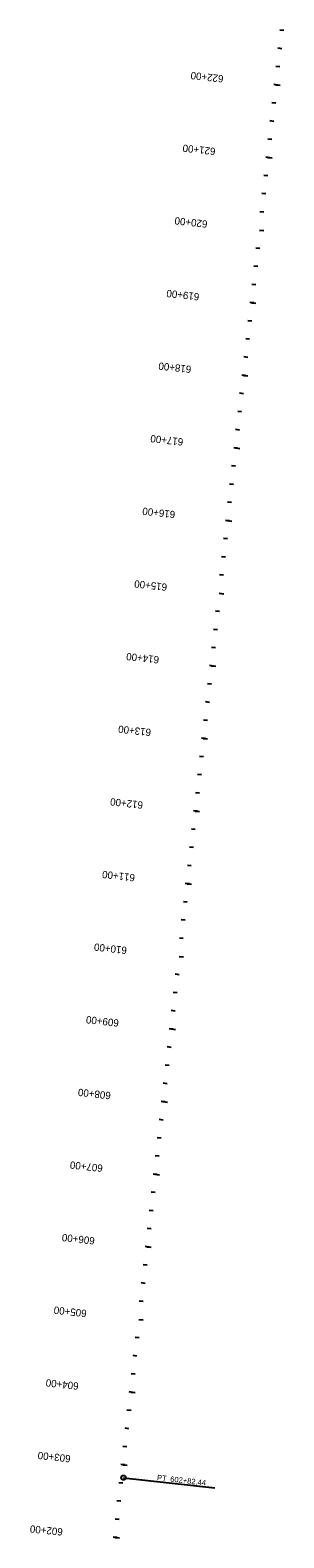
# Model space of a CAD drawing. Extents: x 16453950 to 16454580, y 7022804 to 7039381.
# Drawn here: x 16454058 to 16454406, y 7026953 to 7029017 of the extents above; entities that cross this region are included whole.
import ezdxf

# ---------------------------------------------------------------- set-up
doc = ezdxf.new("R2010")
doc.units = 0
for name, color, linetype in [('TextAlignment', 7, 'Continuous'), ('TextAlignmentLrg', 7, 'Continuous'), ('TextAlignmentSml', 7, 'Continuous')]:
    doc.layers.add(name, color=color, linetype=linetype)

msp = doc.modelspace()

# ---------------------------------------------------------------- linework, layer by layer
at = {"layer": 'TextAlignment'}
for p in [(16454186, 7027035.6), (16454311.2, 7027021.7)]:
    msp.add_line(p, (16454311.2, 7027021.7), dxfattribs=at)
msp.add_circle((16454186, 7027035.6), 3.12, dxfattribs=at)
at = {"layer": 'TextAlignmentLrg'}
for p, q in [((16454397.3, 7028941.5), (16454391.9, 7028942.1)), ((16454386.3, 7028842.1), (16454380.8, 7028842.7)), ((16454372.2, 7028743), (16454378.3, 7028742.3)), ((16454364.2, 7028643.3), (16454358.8, 7028643.9)), ((16454353.2, 7028543.9), (16454347.8, 7028544.5)), ((16454342.2, 7028444.5), (16454336.8, 7028445.1)), ((16454331.2, 7028345.1), (16454325.7, 7028345.7)), ((16454317.1, 7028246.1), (16454323.2, 7028245.4)), ((16454309.1, 7028146.3), (16454303.7, 7028146.9)), ((16454298.1, 7028047), (16454292.7, 7028047.6)), ((16454287.1, 7027947.6), (16454281.7, 7027948.2)), ((16454276.1, 7027848.2), (16454270.6, 7027848.8)), ((16454262, 7027749.1), (16454268.1, 7027748.4)), ((16454254, 7027649.4), (16454248.6, 7027650)), ((16454243, 7027550), (16454237.6, 7027550.6)), ((16454232, 7027450.6), (16454226.6, 7027451.2)), ((16454221, 7027351.2), (16454215.5, 7027351.8)), ((16454206.9, 7027252.2), (16454213, 7027251.5)), ((16454198.9, 7027152.4), (16454193.5, 7027153)), ((16454187.9, 7027053), (16454182.5, 7027053.6)), ((16454177.3, 7026953.6), (16454171.8, 7026954.2))]:
    msp.add_line(p, q, dxfattribs=at)
at = {"layer": 'TextAlignmentSml'}
for p, q in [((16454405.5, 7029016), (16454400.1, 7029016.6)), ((16454402.8, 7028991.2), (16454397.4, 7028991.8)), ((16454400, 7028966.3), (16454394.6, 7028966.9)), ((16454394.2, 7028941.8), (16454400.3, 7028941.1)), ((16454394.5, 7028916.6), (16454389.1, 7028917.2)), ((16454391.8, 7028891.8), (16454386.3, 7028892.4)), ((16454389, 7028866.9), (16454383.6, 7028867.5)), ((16454383.2, 7028842.4), (16454389.3, 7028841.7)), ((16454383.5, 7028817.2), (16454378.1, 7028817.8)), ((16454380.8, 7028792.4), (16454375.3, 7028793)), ((16454378, 7028767.5), (16454372.6, 7028768.1)), ((16454372.2, 7028743), (16454378.3, 7028742.3)), ((16454372.5, 7028717.8), (16454367.1, 7028718.4)), ((16454369.7, 7028693), (16454364.3, 7028693.6)), ((16454367, 7028668.1), (16454361.5, 7028668.7)), ((16454361.2, 7028643.6), (16454367.3, 7028643)), ((16454361.5, 7028618.4), (16454356, 7028619)), ((16454358.7, 7028593.6), (16454353.3, 7028594.2)), ((16454356, 7028568.8), (16454350.5, 7028569.4)), ((16454350.2, 7028544.2), (16454356.2, 7028543.6)), ((16454350.4, 7028519.1), (16454345, 7028519.7)), ((16454347.7, 7028494.2), (16454342.3, 7028494.8)), ((16454344.9, 7028469.4), (16454339.5, 7028470)), ((16454339.1, 7028444.9), (16454345.2, 7028444.2)), ((16454339.4, 7028419.7), (16454334, 7028420.3)), ((16454336.7, 7028394.8), (16454331.2, 7028395.4)), ((16454333.9, 7028370), (16454328.5, 7028370.6)), ((16454328.1, 7028345.5), (16454334.2, 7028344.8)), ((16454328.4, 7028320.3), (16454323, 7028320.9)), ((16454325.7, 7028295.4), (16454320.2, 7028296)), ((16454322.9, 7028270.6), (16454317.5, 7028271.2)), ((16454317.1, 7028246.1), (16454323.2, 7028245.4)), ((16454317.4, 7028220.9), (16454312, 7028221.5)), ((16454314.6, 7028196), (16454309.2, 7028196.6)), ((16454311.9, 7028171.2), (16454306.4, 7028171.8)), ((16454306.1, 7028146.7), (16454312.2, 7028146)), ((16454306.4, 7028121.5), (16454300.9, 7028122.1)), ((16454303.6, 7028096.6), (16454298.2, 7028097.2)), ((16454300.9, 7028071.8), (16454295.4, 7028072.4)), ((16454295.1, 7028047.3), (16454301.1, 7028046.6)), ((16454295.3, 7028022.1), (16454289.9, 7028022.7)), ((16454292.6, 7027997.3), (16454287.2, 7027997.9)), ((16454289.8, 7027972.4), (16454284.4, 7027973)), ((16454284, 7027947.9), (16454290.1, 7027947.2)), ((16454284.3, 7027922.7), (16454278.9, 7027923.3)), ((16454281.6, 7027897.9), (16454276.1, 7027898.5)), ((16454278.8, 7027873), (16454273.4, 7027873.6)), ((16454273, 7027848.5), (16454279.1, 7027847.8)), ((16454273.3, 7027823.3), (16454267.9, 7027823.9)), ((16454270.6, 7027798.5), (16454265.1, 7027799.1)), ((16454267.8, 7027773.6), (16454262.4, 7027774.2)), ((16454262, 7027749.1), (16454268.1, 7027748.4)), ((16454262.3, 7027723.9), (16454256.9, 7027724.5)), ((16454259.5, 7027699.1), (16454254.1, 7027699.7)), ((16454256.8, 7027674.2), (16454251.3, 7027674.8)), ((16454251, 7027649.7), (16454257.1, 7027649)), ((16454251.3, 7027624.5), (16454245.8, 7027625.1)), ((16454248.5, 7027599.7), (16454243.1, 7027600.3)), ((16454245.8, 7027574.8), (16454240.3, 7027575.4)), ((16454240, 7027550.3), (16454246, 7027549.7)), ((16454240.2, 7027525.1), (16454234.8, 7027525.7)), ((16454237.5, 7027500.3), (16454232.1, 7027500.9)), ((16454234.7, 7027475.5), (16454229.3, 7027476.1)), ((16454228.9, 7027450.9), (16454235, 7027450.3)), ((16454229.2, 7027425.8), (16454223.8, 7027426.4)), ((16454226.5, 7027400.9), (16454221, 7027401.5)), ((16454223.7, 7027376.1), (16454218.3, 7027376.7)), ((16454217.9, 7027351.6), (16454224, 7027350.9)), ((16454218.2, 7027326.4), (16454212.8, 7027327)), ((16454215.4, 7027301.5), (16454210, 7027302.1)), ((16454212.7, 7027276.7), (16454207.3, 7027277.3)), ((16454206.9, 7027252.2), (16454213, 7027251.5)), ((16454207.2, 7027227), (16454201.8, 7027227.6)), ((16454204.4, 7027202.1), (16454199, 7027202.7)), ((16454201.7, 7027177.3), (16454196.2, 7027177.9)), ((16454195.9, 7027152.8), (16454202, 7027152.1)), ((16454196.2, 7027127.6), (16454190.7, 7027128.2)), ((16454193.4, 7027102.7), (16454188, 7027103.3)), ((16454190.7, 7027077.9), (16454185.2, 7027078.5)), ((16454184.9, 7027053.4), (16454190.9, 7027052.7)), ((16454185.1, 7027028.2), (16454179.7, 7027028.8)), ((16454182.4, 7027003.3), (16454177, 7027003.9)), ((16454179.8, 7026978.5), (16454174.4, 7026979)), ((16454174.2, 7026953.9), (16454180.3, 7026953.3))]:
    msp.add_line(p, q, dxfattribs=at)

# ---------------------------------------------------------------- texts
at = {"layer": 'TextAlignment'}
for s, p in [('PT', (16454231.5, 7027032.2)), ('602+82.44', (16454249.6, 7027030.2))]:
    msp.add_text(s, height=7.5, rotation=353.6731, dxfattribs=at).set_placement(p)
at = {"layer": 'TextAlignmentLrg'}
for s, p in [('620+00', (16454301.3, 7028755.9)), ('615+00', (16454246.1, 7028259)), ('610+00', (16454191, 7027762)), ('605+00', (16454135.9, 7027265.1))]:
    msp.add_text(s, height=10.02, rotation=173.6731, dxfattribs=at).set_placement(p)
at = {"layer": 'TextAlignmentSml'}
for s, rotation, p in [('622+00', 173.6731, (16454323.3, 7028954.7)), ('621+00', 173.6731, (16454312.3, 7028855.3)), ('620+00', 173.6731, (16454301.3, 7028755.9)), ('619+00', 173.6731, (16454290.2, 7028656.5)), ('618+00', 173.6731, (16454279.2, 7028557.1)), ('617+00', 173.6731, (16454268.2, 7028457.8)), ('616+00', 173.6731, (16454257.2, 7028358.4)), ('615+00', 173.6731, (16454246.1, 7028259)), ('614+00', 173.6731, (16454235.1, 7028159.6)), ('613+00', 173.6731, (16454224.1, 7028060.2)), ('612+00', 173.6731, (16454213.1, 7027960.8)), ('611+00', 173.6731, (16454202.1, 7027861.4)), ('610+00', 173.6731, (16454191, 7027762)), ('609+00', 173.6731, (16454180, 7027662.6)), ('608+00', 173.6731, (16454169, 7027563.2)), ('607+00', 173.6731, (16454158, 7027463.8)), ('606+00', 173.6731, (16454147, 7027364.5)), ('605+00', 173.6731, (16454135.9, 7027265.1)), ('604+00', 173.6731, (16454124.9, 7027165.7)), ('603+00', 173.6731, (16454113.9, 7027066.3)), ('602+00', 174.2226, (16454103.2, 7026966.1))]:
    msp.add_text(s, height=10.02, rotation=rotation, dxfattribs=at).set_placement(p)

doc.saveas('drawing.dxf')
